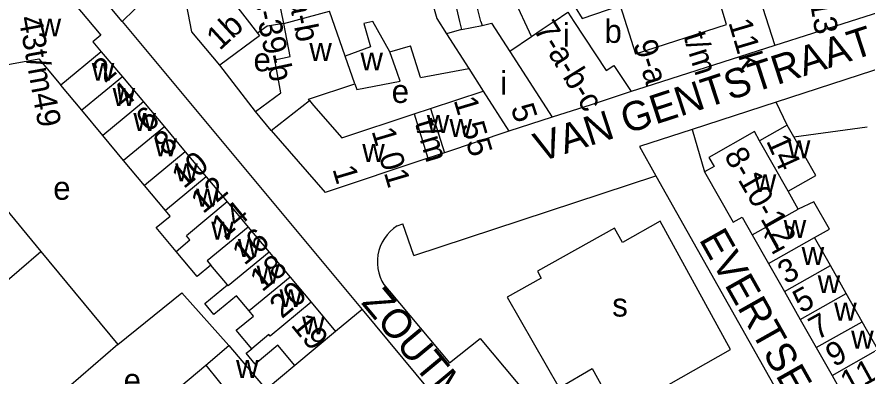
# Model space of a CAD drawing. Extents: x 159902 to 161769, y 383692 to 384875.
# Drawn here: x 160740.8 to 160886.5, y 384439.2 to 384500.8 of the extents above; entities that cross this region are included whole.
import ezdxf

# ---------------------------------------------------------------- set-up
doc = ezdxf.new("R2010")
doc.units = 0
for name, color, linetype in [('BLT_Basislijn', 7, 'Continuous'), ('BLT_Bebouwing', 7, 'Continuous'), ('BLT_Centroide', 7, 'Continuous'), ('BLT_Huisnummer', 7, 'Continuous'), ('BLT_Huisnummer_ tussenligend', 7, 'Continuous'), ('BLT_Huisnummer_reeks', 7, 'Continuous'), ('BLT_Onderdoorgang_en_onderverdeling', 7, 'Continuous'), ('BLT_Onderverdeling_panden', 7, 'Continuous'), ('BLT_Straatnaam', 7, 'Continuous'), ('BLT_Vlakafsluiter', 7, 'Continuous')]:
    doc.layers.add(name, color=color, linetype=linetype)

msp = doc.modelspace()

# ---------------------------------------------------------------- linework, layer by layer
at = {"layer": 'BLT_Basislijn'}
for p, q in [((160758.87, 384500), (160799.98, 384450.61)), ((160892.74, 384493.27), (160870.95, 384486.16)), ((160781.73, 384484.55), (160775.61, 384492.48)), ((160870.95, 384486.16), (160856.55, 384481.47)), ((160872.86, 384482.21), (160870.95, 384486.16)), ((160856.55, 384481.47), (160847.53, 384478.53)), ((160856.55, 384481.47), (160858.7, 384474.2)), ((160847.53, 384478.53), (160850.36, 384473.5)), ((160808.85, 384459.85), (160850.36, 384473.5)), ((160850.36, 384473.5), (160872.85, 384433.55)), ((160805.98, 384464.92), (160806.99, 384465.3)), ((160808.85, 384459.85), (160806.99, 384465.3)), ((160731.05, 384448.61), (160744.94, 384460.54)), ((160744.94, 384460.54), (160758.1, 384444.6)), ((160803.7, 384454.86), (160804.61, 384453.78)), ((160804.61, 384453.78), (160815, 384441.44)), ((160758.1, 384444.6), (160769.12, 384453.45)), ((160769.12, 384453.45), (160777.17, 384444.42)), ((160799.98, 384450.61), (160795.45, 384446.81)), ((160799.98, 384450.61), (160811.45, 384436.83)), ((160788.44, 384440.97), (160783.58, 384436.86))]:
    msp.add_line(p, q, dxfattribs=at)
for points in [[(160758.87, 384500), (160751.1, 384509.34), (160700, 384500.18)], [(160707.33, 384486.73), (160716.95, 384475.77), (160730.27, 384478.33), (160744.94, 384460.54)], [(160873.99, 384480.2), (160886.59, 384481.92)], [(160851.07, 384465.72), (160844.62, 384462.09), (160843.27, 384464.56), (160830.04, 384457.14), (160830.7, 384455.97), (160824.85, 384452.69), (160833.78, 384437.17), (160839.42, 384440.49), (160843.73, 384432.71), (160863.16, 384443.74), (160851.07, 384465.72)], [(160805.98, 384464.92), (160805.36, 384464.47), (160804.78, 384463.96), (160804.27, 384463.39), (160803.81, 384462.78), (160803.43, 384462.11), (160803.11, 384461.41), (160802.87, 384460.68), (160802.7, 384459.94), (160802.62, 384459.17), (160802.61, 384458.41), (160802.68, 384457.64), (160802.84, 384456.89), (160803.07, 384456.16), (160803.37, 384455.45), (160803.7, 384454.86)], [(160815, 384441.44), (160820.26, 384445.6), (160847.56, 384412.99)], [(160758.1, 384444.6), (160749.65, 384437.26), (160752.56, 384433.91)]]:
    msp.add_lwpolyline(points, dxfattribs=at)
at = {"layer": 'BLT_Bebouwing'}
for p, q in [((160824.99, 384506.1), (160829.02, 384497.37)), ((160890.42, 384502.17), (160883.63, 384500)), ((160832.91, 384500), (160835.25, 384501.58)), ((160804.73, 384494.79), (160801.83, 384499.99)), ((160832.91, 384500), (160830.87, 384498.62)), ((160883.63, 384500), (160870.76, 384495.85)), ((160830.87, 384498.62), (160829.02, 384497.37)), ((160755.27, 384494.77), (160758.91, 384490.51)), ((160809.98, 384490.37), (160818.27, 384491.91)), ((160818.27, 384491.91), (160820.76, 384488.02)), ((160758.91, 384490.51), (160762.51, 384486.21)), ((160751.95, 384484.76), (160748.37, 384489.06)), ((160762.51, 384486.21), (160766.1, 384481.92)), ((160755.54, 384480.45), (160751.95, 384484.76)), ((160784.43, 384481.31), (160781.73, 384484.55)), ((160839.24, 384485.71), (160832.59, 384483.56)), ((160832.59, 384483.56), (160825.15, 384481.16)), ((160766.1, 384481.92), (160769.69, 384477.62)), ((160759.12, 384476.15), (160755.54, 384480.45)), ((160784.43, 384481.31), (160793.69, 384470.64)), ((160825.15, 384481.16), (160814.13, 384477.48)), ((160769.69, 384477.62), (160773.28, 384473.32)), ((160814.13, 384477.48), (160811.27, 384476.52)), ((160762.71, 384471.85), (160759.12, 384476.15)), ((160811.27, 384476.52), (160793.69, 384470.64)), ((160773.28, 384473.32), (160776.87, 384469.03)), ((160766.29, 384467.55), (160762.71, 384471.85)), ((160874.77, 384467.81), (160873.03, 384470.88)), ((160776.87, 384469.03), (160780.46, 384464.73)), ((160865.15, 384466.45), (160866.88, 384463.39)), ((160780.46, 384464.73), (160784.06, 384460.43)), ((160866.88, 384463.39), (160869.67, 384458.46)), ((160880.26, 384458.12), (160877.54, 384462.92)), ((160784.06, 384460.43), (160787.65, 384456.14)), ((160776.9, 384454.81), (160774.07, 384458.2)), ((160869.67, 384458.46), (160872.39, 384453.66)), ((160882.98, 384453.31), (160880.26, 384458.12)), ((160787.65, 384456.14), (160791.24, 384451.84)), ((160872.39, 384453.66), (160875.11, 384448.86)), ((160885.71, 384448.48), (160882.98, 384453.31)), ((160791.24, 384451.84), (160795.45, 384446.81)), ((160875.11, 384448.86), (160877.83, 384444.06)), ((160888.42, 384443.71), (160885.71, 384448.48)), ((160795.45, 384446.81), (160788.44, 384440.97)), ((160773.2, 384441.04), (160777.17, 384444.42)), ((160777.17, 384444.42), (160782.94, 384437.61)), ((160877.83, 384444.06), (160880.55, 384439.25)), ((160768.93, 384437.42), (160773.2, 384441.04)), ((160880.55, 384439.25), (160883.27, 384434.45))]:
    msp.add_line(p, q, dxfattribs=at)
for points in [[(160775.61, 384492.48), (160770.82, 384498.23), (160768.62, 384509.5)], [(160816.64, 384506.53), (160816.98, 384505.05), (160815.63, 384504.74), (160816.7, 384500)], [(160862.48, 384499.49), (160860.41, 384506.33), (160867.05, 384507.42)], [(160733.41, 384501.57), (160743.97, 384503.51), (160746.35, 384505.48), (160747.44, 384504.14), (160749.48, 384504.51), (160755.21, 384497.65), (160753.83, 384496.49), (160755.27, 384494.77)], [(160809.19, 384505.06), (160811.36, 384505.53), (160812.79, 384500.48)], [(160836.49, 384502.42), (160837.69, 384500.5), (160844.24, 384502.72)], [(160844.24, 384502.72), (160846.87, 384494.44), (160862.48, 384499.49)], [(160797.1, 384494.01), (160794.41, 384501.77)], [(160812.79, 384500.48), (160814.48, 384497.84)], [(160781.73, 384484.55), (160786.05, 384487.76), (160785.02, 384493.41), (160787.69, 384493.98), (160786.57, 384499.65)], [(160786.57, 384499.65), (160783.75, 384499.18), (160782.07, 384497.98)], [(160801.83, 384499.99), (160800.3, 384499.64), (160801.45, 384495.66), (160797.1, 384494.01)], [(160816.7, 384500), (160817.02, 384498.6)], [(160782.07, 384497.98), (160782.43, 384497.52), (160775.61, 384492.48)], [(160817.02, 384498.6), (160814.48, 384497.84)], [(160814.48, 384497.84), (160818.27, 384491.91)], [(160804.73, 384494.79), (160808.29, 384495.81)], [(160806.51, 384489.74), (160806.02, 384491.24), (160804.73, 384494.79)], [(160809.98, 384490.37), (160808.29, 384495.81)], [(160870.76, 384495.85), (160848.46, 384488.73), (160846.12, 384487.96)], [(160735.18, 384491.85), (160744.6, 384493.58), (160748.37, 384489.06)], [(160791, 384486.44), (160790.83, 384486.66), (160798.74, 384489.27)], [(160798.74, 384489.27), (160799.07, 384488.34), (160806.51, 384489.74)], [(160811.73, 384485.05), (160820.76, 384488.02)], [(160846.12, 384487.96), (160839.24, 384485.71)], [(160791, 384486.44), (160791.68, 384485.6), (160796.53, 384480.04), (160808.92, 384484.12)], [(160808.92, 384484.12), (160811.73, 384485.05)], [(160872.86, 384482.21), (160868.13, 384479.52)], [(160873.99, 384480.2), (160872.86, 384482.21)], [(160868.13, 384479.52), (160867.26, 384481.11), (160859.42, 384476.65), (160860.33, 384475.11), (160858.7, 384474.2)], [(160873.03, 384470.88), (160877.76, 384473.55), (160873.99, 384480.2)], [(160858.7, 384474.2), (160863.59, 384465.55), (160865.15, 384466.45)], [(160877.54, 384462.92), (160880.09, 384464.36), (160877.45, 384469.03), (160874.77, 384467.81)], [(160768.11, 384460.54), (160764.71, 384464.63), (160767.07, 384466.61), (160766.29, 384467.55)], [(160774.07, 384458.2), (160771.71, 384456.23), (160768.11, 384460.54)], [(160780.63, 384450.34), (160778.44, 384452.96), (160774.6, 384449.75), (160773.06, 384451.59), (160776.9, 384454.81)], [(160781.07, 384443.85), (160778.43, 384447.03), (160781.36, 384449.46), (160780.63, 384450.34)], [(160788.44, 384440.97), (160785.53, 384444.45), (160781.69, 384441.24), (160780.15, 384443.08), (160781.07, 384443.85)]]:
    msp.add_lwpolyline(points, dxfattribs=at)
at = {"layer": 'BLT_Onderdoorgang_en_onderverdeling'}
for p, q in [((160811.73, 384485.05), (160814.13, 384477.48)), ((160808.92, 384484.12), (160811.27, 384476.52))]:
    msp.add_line(p, q, dxfattribs=at)
at = {"layer": 'BLT_Onderverdeling_panden'}
for p, q in [((160786.57, 384499.65), (160784.03, 384512.55)), ((160820.36, 384500), (160818.51, 384507.17)), ((160867.05, 384507.42), (160870.76, 384495.85)), ((160777.73, 384503.59), (160782.07, 384497.98)), ((160786.57, 384499.65), (160794.41, 384501.77)), ((160835.25, 384501.58), (160836.29, 384500)), ((160817.02, 384498.6), (160820.55, 384499.32)), ((160820.36, 384500), (160820.55, 384499.32)), ((160829.02, 384497.37), (160825.3, 384494.86)), ((160755.27, 384494.77), (160748.37, 384489.06)), ((160825.3, 384494.86), (160832.59, 384483.56)), ((160798.74, 384489.27), (160797.1, 384494.01)), ((160758.91, 384490.51), (160751.95, 384484.76)), ((160820.76, 384488.02), (160825.15, 384481.16)), ((160762.51, 384486.21), (160755.54, 384480.45)), ((160784.43, 384481.31), (160791, 384486.44)), ((160766.1, 384481.92), (160759.12, 384476.15)), ((160873.03, 384470.88), (160868.13, 384479.52)), ((160769.69, 384477.62), (160762.71, 384471.85)), ((160773.28, 384473.32), (160766.29, 384467.55)), ((160776.87, 384469.03), (160769.87, 384463.24)), ((160866.88, 384463.39), (160874.77, 384467.81)), ((160869.67, 384458.46), (160877.54, 384462.92)), ((160872.39, 384453.66), (160880.26, 384458.12)), ((160787.65, 384456.14), (160780.63, 384450.34)), ((160875.11, 384448.86), (160882.98, 384453.31)), ((160877.83, 384444.06), (160885.71, 384448.48)), ((160880.55, 384439.25), (160888.42, 384443.71)), ((160773.2, 384441.04), (160779.46, 384433.36))]:
    msp.add_line(p, q, dxfattribs=at)
for points in [[(160820.55, 384499.32), (160822.16, 384499.7), (160825.3, 384494.86)], [(160836.29, 384500), (160841.83, 384491.58), (160843.16, 384492.46), (160846.12, 384487.96)], [(160780.46, 384464.73), (160773.46, 384458.94), (160774.07, 384458.2)], [(160768.11, 384460.54), (160770.48, 384462.51), (160769.87, 384463.24)], [(160784.06, 384460.43), (160777.04, 384454.64), (160776.9, 384454.81)], [(160791.24, 384451.84), (160784.21, 384446.03), (160783.99, 384446.29), (160781.07, 384443.85)]]:
    msp.add_lwpolyline(points, dxfattribs=at)
at = {"layer": 'BLT_Vlakafsluiter'}
msp.add_line((160758.87, 384500), (160768.62, 384509.5), dxfattribs=at)

# ---------------------------------------------------------------- texts
at = {"layer": 'BLT_Centroide'}
for s, p in [('w', (160744.55, 384497.41)), ('b', (160841.54, 384496.32)), ('i', (160834.4, 384495.66)), ('w', (160790.95, 384493.23)), ('e', (160781.38, 384491.44)), ('w', (160799.71, 384491.59)), ('w', (160753.66, 384489.81)), ('i', (160823.66, 384487.45)), ('e', (160805.06, 384486.01)), ('w', (160757.23, 384485.5)), ('w', (160760.8, 384481.19)), ('w', (160811.09, 384480.87)), ('w', (160814.97, 384480.18)), ('w', (160764.38, 384476.88)), ('w', (160800.02, 384475.91)), ('w', (160872.97, 384476.52)), ('w', (160767.96, 384472.56)), ('w', (160867.14, 384470.72)), ('e', (160747.05, 384469.41)), ('w', (160771.54, 384468.25)), ('w', (160774.14, 384462.59)), ('w', (160872.26, 384462.86)), ('w', (160778.69, 384459.62)), ('w', (160875.34, 384458.23)), ('w', (160781.91, 384455.03)), ('w', (160878.09, 384453.39)), ('w', (160785.84, 384451)), ('s', (160842.87, 384449.38)), ('w', (160880.91, 384448.69)), ('w', (160789.71, 384446.31)), ('w', (160883.82, 384443.89)), ('w', (160778.39, 384438.83)), ('e', (160759.11, 384436.46))]:
    msp.add_text(s, height=4, dxfattribs=at).set_placement(p)
at = {"layer": 'BLT_Huisnummer'}
for s, rotation, p in [('13', 279.388, (160876.74, 384503.44)), ('1b', 42.612, (160775.56, 384494.88)), ('2', 39.5642, (160755.89, 384489.32)), ('5', 288.388, (160825.43, 384485.17)), ('6', 39.5642, (160763.29, 384480.83)), ('14', 294.2224, (160869.2, 384479.52)), ('10', 39.5642, (160769.43, 384471.18)), ('14', 39.5642, (160776.28, 384462.59)), ('1', 28.7646, (160870.09, 384459.86)), ('20', 39.5642, (160786.23, 384448.9)), ('5', 28.7646, (160875.26, 384449.87)), ('19', 309.2017, (160787.66, 384447.87)), ('9', 28.7646, (160880.87, 384440.64))]:
    msp.add_text(s, height=4, rotation=rotation, dxfattribs=at).set_placement(p)
at = {"layer": 'BLT_Huisnummer_ tussenligend'}
for s, rotation, p in [('4', 39.5642, (160759.17, 384485.01)), ('8', 39.5642, (160766.33, 384476.79)), ('12', 39.5642, (160772.73, 384466.89)), ('16', 39.5642, (160779.82, 384458.04)), ('18', 39.5642, (160782.86, 384453.49)), ('3', 28.7646, (160872.66, 384454.82)), ('7', 28.7646, (160877.98, 384445.28)), ('11', 28.7646, (160883.39, 384435.97))]:
    msp.add_text(s, height=4, rotation=rotation, dxfattribs=at).set_placement(p)
at = {"layer": 'BLT_Huisnummer_reeks'}
for s, rotation, p in [('37c-39-b', 282.1496, (160779.93, 384510.04)), ('37a-b', 281.1509, (160786.25, 384509.66)), ('43t/m49', 280.3225, (160741.09, 384500.62)), ('7-a-b-c', 301.7927, (160829.28, 384498.59)), ('11k', 286.5105, (160862.75, 384499.84)), ('t/m', 287.2377, (160855.04, 384497.54)), ('9-a', 287.2377, (160846.45, 384496.18)), ('1 55', 286.5105, (160815.66, 384486.5)), ('t/m', 286.5105, (160808.99, 384482.68)), ('1 01', 286.5105, (160801.59, 384481.2)), ('8-10-12', 299.9724, (160861.95, 384476.99)), ('1', 286.5105, (160794.88, 384474.69))]:
    msp.add_text(s, height=4, rotation=rotation, dxfattribs=at).set_placement(p)
at = {"layer": 'BLT_Straatnaam'}
for s, rotation, p in [('VAN GENTSTRAAT', 18.0353, (160830.48, 384475.84)), ('EVERTSENSTRAAT', 299.401, (160857.66, 384462.62)), ('ZOUTMANSTRAAT', 309.7698, (160799.72, 384451.71))]:
    msp.add_text(s, height=5, rotation=rotation, dxfattribs=at).set_placement(p)

doc.saveas('drawing.dxf')
